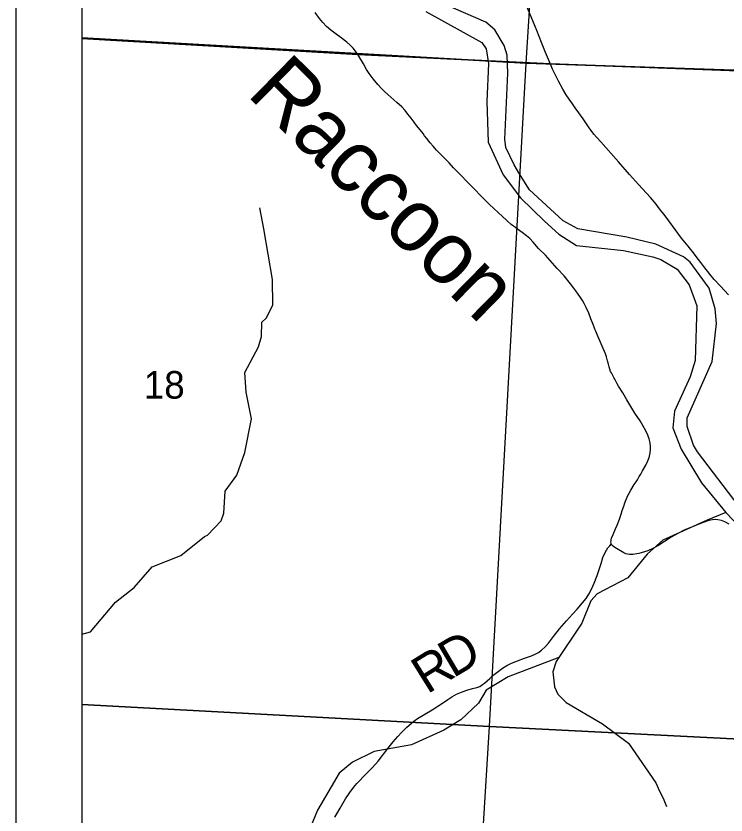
# Model space of a CAD drawing. Extents: x 21.4 to 65.3, y 4 to 26.
# Drawn here: x 23.447 to 24.526, y 19.377 to 20.591 of the extents above; entities that cross this region are included whole.
import ezdxf

# ---------------------------------------------------------------- set-up
doc = ezdxf.new("R2010")
doc.units = 0
for name, color, linetype in [('Default', 7, 'Continuous'), ('GM_X_County_Road', 7, 'Continuous'), ('GM_X_Major_River', 7, 'Continuous'), ('GM_X_Major_River_Text', 7, 'Continuous'), ('GM_X_Minor_River', 7, 'Continuous'), ('GM_X_Section', 7, 'Continuous'), ('GM_X_Section_Text', 7, 'Continuous'), ('GM_X_Township_Road', 7, 'Continuous'), ('GM_X_Township_Road_Text', 7, 'Continuous'), ('SH_Cut_Line', 7, 'Continuous'), ('SH_Data', 7, 'Continuous')]:
    doc.layers.add(name, color=color, linetype=linetype)

msp = doc.modelspace()

# ---------------------------------------------------------------- linework, layer by layer
at = {"layer": 'Default'}
msp.add_lwpolyline([(23.5473, 24.8542), (23.5473, 20.5568), (23.9671, 20.5321), (24.2595, 20.5181), (24.9947, 20.491), (25.2828, 20.4818), (25.7909, 20.4519), (25.8002, 20.4525), (25.809, 20.4526), (25.8187, 20.4522), (25.831, 20.4509), (25.8341, 20.4506), (25.8391, 20.4499), (25.8459, 20.4493), (25.8552, 20.4488), (25.869, 20.4484), (25.878, 20.4484)], dxfattribs=at)
for points in [[(23.5473, 21.5732), (23.5473, 20.5578), (24.2227, 20.5192), (24.2858, 21.5075)], [(23.5473, 20.5578), (23.5473, 19.545), (24.1671, 19.5117), (24.2227, 20.5192)], [(23.5473, 20.5568), (23.5473, 18.0542), (25.1151, 18.0542), (25.1319, 18.358), (25.2037, 19.5236), (25.229, 19.8268), (25.2761, 20.4088), (25.2828, 20.4818), (24.9947, 20.491), (24.2595, 20.5181), (23.9671, 20.5321)], [(23.5473, 19.545), (23.5473, 18.5459), (24.1059, 18.5148), (24.1671, 19.5117)]]:
    msp.add_lwpolyline(points, close=True, dxfattribs=at)
at = {"layer": 'GM_X_County_Road'}
for points in [[(24.2597, 20.5175), (24.252, 20.5351), (24.2459, 20.5506), (24.2423, 20.5598), (24.2389, 20.5686), (24.2363, 20.5747), (24.2227, 20.6076)], [(24.5303, 20.1673), (24.5179, 20.1804), (24.5087, 20.1905), (24.5019, 20.1985), (24.493, 20.2101), (24.4883, 20.2163), (24.4813, 20.2254), (24.477, 20.2311), (24.4687, 20.2412), (24.459, 20.2532), (24.4397, 20.2795), (24.4339, 20.2872), (24.4256, 20.2981), (24.4205, 20.3048), (24.4116, 20.3149), (24.3933, 20.3349), (24.38, 20.35), (24.3632, 20.3693), (24.336, 20.3996), (24.3302, 20.4061), (24.3256, 20.4113), (24.3216, 20.4168), (24.3184, 20.4211), (24.3092, 20.4346), (24.3029, 20.4436), (24.2974, 20.4514), (24.2922, 20.4587), (24.288, 20.4645), (24.2835, 20.4712), (24.2783, 20.4796), (24.2719, 20.4916), (24.2672, 20.501), (24.263, 20.51), (24.2597, 20.5175)]]:
    msp.add_lwpolyline(points, dxfattribs=at)
at = {"layer": 'GM_X_Major_River'}
for points in [[(24.0704, 20.5978), (24.1553, 20.5506), (24.1618, 20.5408), (24.1653, 20.5188), (24.1628, 20.4607), (24.1652, 20.3989), (24.1877, 20.3496), (24.214, 20.3144), (24.2504, 20.2793), (24.2725, 20.2596), (24.299, 20.2423), (24.3707, 20.2345), (24.4154, 20.2248), (24.4275, 20.2211), (24.4522, 20.2064), (24.4704, 20.1825), (24.4823, 20.1507), (24.4795, 20.0676), (24.472, 20.0429), (24.4483, 19.9904), (24.4457, 19.965), (24.4583, 19.9328), (24.4891, 19.8817), (24.5262, 19.8365)], [(24.5463, 19.8457), (24.4833, 19.9287), (24.4772, 19.9389), (24.4673, 19.9674), (24.4672, 19.9803), (24.5052, 20.0662), (24.5119, 20.1239), (24.5099, 20.1459), (24.5008, 20.1773), (24.4719, 20.2171), (24.4616, 20.225), (24.4199, 20.2442), (24.3755, 20.2547), (24.3012, 20.2673), (24.2792, 20.2798), (24.228, 20.3266), (24.2116, 20.3527), (24.2044, 20.3645), (24.1918, 20.391), (24.1902, 20.4035), (24.1949, 20.5037), (24.1937, 20.5314), (24.1895, 20.5458), (24.175, 20.5697), (24.1613, 20.5814), (24.0972, 20.6092)], [(24.5262, 19.8365), (24.5801, 19.7802)]]:
    msp.add_lwpolyline(points, dxfattribs=at)
at = {"layer": 'GM_X_Minor_River'}
for points in [[(23.7632, 19.8356), (23.7654, 19.8691), (23.7828, 19.8931), (23.795, 19.9277), (23.8052, 19.9791), (23.7973, 20.0194), (23.7954, 20.0494), (23.8159, 20.0882), (23.8204, 20.1038), (23.8212, 20.1258), (23.8277, 20.1316), (23.8375, 20.1517), (23.8372, 20.1905), (23.8239, 20.2677), (23.8179, 20.2996)], [(23.5473, 19.6518), (23.5607, 19.6555), (23.5987, 19.7002), (23.627, 19.7228), (23.6544, 19.7542), (23.6977, 19.7715), (23.7337, 19.7999), (23.7383, 19.8021), (23.759, 19.8238), (23.7632, 19.8358)], [(24.5262, 19.8365), (24.4979, 19.825), (24.4302, 19.7946), (24.4064, 19.7732), (24.3774, 19.7374), (24.3657, 19.7313), (24.3305, 19.7132), (24.3211, 19.7022), (24.3072, 19.6687), (24.2685, 19.6104), (24.2633, 19.5944), (24.2657, 19.5716), (24.2711, 19.5607), (24.2837, 19.5478), (24.3389, 19.5154), (24.3782, 19.486), (24.4199, 19.4262), (24.4253, 19.4134), (24.4311, 19.4028), (24.4361, 19.3902)], [(24.2725, 19.6164), (24.1954, 19.5872), (24.1621, 19.5669), (24.1505, 19.5468), (24.1233, 19.5219), (24.0976, 19.5059), (24.0484, 19.4836), (23.9919, 19.4738), (23.9586, 19.4573), (23.9386, 19.4409), (23.9056, 19.3845), (23.8914, 19.3502)]]:
    msp.add_lwpolyline(points, dxfattribs=at)
at = {"layer": 'GM_X_Section'}
for points in [[(25.3384, 21.4821), (25.275, 20.4836), (24.2227, 20.5192), (24.2858, 21.5075), (24.7985, 21.5074)], [(24.2227, 20.5192), (25.275, 20.4836), (25.2871, 20.4832), (25.208, 19.459), (24.1671, 19.5117)], [(24.1671, 19.5117), (25.208, 19.459), (25.1472, 18.4529), (24.1059, 18.5148)]]:
    msp.add_lwpolyline(points, close=True, dxfattribs=at)
at = {"layer": 'GM_X_Township_Road'}
for points in [[(23.9662, 20.5332), (23.9635, 20.5372), (23.9597, 20.542), (23.9554, 20.5464), (23.9503, 20.5508), (23.9415, 20.5576), (23.9395, 20.5591), (23.936, 20.5616), (23.9261, 20.5692), (23.9195, 20.575), (23.9139, 20.5808), (23.9088, 20.5871), (23.9022, 20.5962)], [(24.5312, 19.8188), (24.5246, 19.8222), (24.5195, 19.8242), (24.5141, 19.8256), (24.5099, 19.8261), (24.5057, 19.8257), (24.5004, 19.8245), (24.4916, 19.8213), (24.479, 19.8161), (24.4631, 19.8096), (24.4531, 19.8047), (24.4429, 19.7991), (24.4229, 19.7858), (24.4151, 19.7817), (24.4077, 19.7786), (24.4027, 19.7769), (24.3976, 19.7752), (24.3939, 19.7743), (24.3909, 19.7736), (24.3879, 19.7732), (24.3847, 19.7728), (24.3797, 19.7728), (24.3765, 19.7732), (24.374, 19.7738), (24.3712, 19.7751), (24.3573, 19.7834), (24.3553, 19.785), (24.3536, 19.7863), (24.3527, 19.7874), (24.3521, 19.7886), (24.3517, 19.7901), (24.3516, 19.7919), (24.3517, 19.7939), (24.3519, 19.7956), (24.3526, 19.7976), (24.3548, 19.8031), (24.3558, 19.8057), (24.3584, 19.8116), (24.3611, 19.8176), (24.3644, 19.8267), (24.367, 19.8339), (24.3688, 19.8394), (24.3711, 19.8462), (24.3729, 19.8512), (24.3746, 19.8562), (24.3772, 19.8626), (24.3791, 19.8658), (24.3818, 19.8707), (24.3871, 19.8791), (24.3898, 19.8833), (24.3917, 19.8864), (24.3947, 19.8911), (24.3969, 19.8949), (24.3997, 19.8997), (24.4045, 19.9084), (24.4077, 19.915), (24.4096, 19.9202), (24.4112, 19.9268), (24.4119, 19.9323), (24.4118, 19.9371), (24.4111, 19.9426), (24.4096, 19.9485), (24.4074, 19.9542), (24.4044, 19.9608), (24.3999, 19.9686), (24.3959, 19.9757), (24.388, 19.9876), (24.3756, 20.0078), (24.3695, 20.0186), (24.3633, 20.0287), (24.3608, 20.0323), (24.3576, 20.0389), (24.3567, 20.0405), (24.3556, 20.0426), (24.3533, 20.0469), (24.3522, 20.049), (24.3511, 20.051), (24.35, 20.0545), (24.349, 20.058), (24.348, 20.0617), (24.3464, 20.0671), (24.3447, 20.073), (24.3431, 20.0776), (24.3417, 20.0813), (24.3399, 20.0857), (24.3337, 20.0999), (24.3318, 20.1044), (24.3297, 20.1093), (24.3285, 20.1121), (24.3273, 20.115), (24.3259, 20.1183), (24.3244, 20.1222), (24.3211, 20.131), (24.3181, 20.1395), (24.3141, 20.148), (24.3108, 20.1541), (24.3082, 20.1586), (24.3054, 20.1631), (24.3017, 20.1685), (24.2984, 20.1733), (24.2951, 20.1776), (24.2901, 20.1841), (24.2804, 20.1963), (24.27, 20.2073), (24.2521, 20.2273), (24.2417, 20.2376), (24.2336, 20.2472), (24.2284, 20.2528), (24.2233, 20.2568), (24.2165, 20.2618), (24.213, 20.2645), (24.2096, 20.267), (24.2064, 20.2695), (24.2019, 20.2728), (24.2, 20.2743), (24.1944, 20.2792), (24.193, 20.2805), (24.1866, 20.2863), (24.1668, 20.3043), (24.1594, 20.3118), (24.1387, 20.3331), (24.1181, 20.3545), (24.1124, 20.3603), (24.1056, 20.3675), (24.1004, 20.3728), (24.0939, 20.3795), (24.0866, 20.3871), (24.0812, 20.3929), (24.0769, 20.398), (24.0716, 20.4045), (24.0684, 20.4088), (24.066, 20.4121), (24.0592, 20.4209), (24.0563, 20.4247), (24.0526, 20.4293), (24.0478, 20.4356), (24.0431, 20.4419), (24.0389, 20.4472), (24.0338, 20.4526), (24.0264, 20.4592), (24.017, 20.4673), (24.0123, 20.4714), (24.0074, 20.4761), (24.0022, 20.4814), (23.9973, 20.4868), (23.9903, 20.4952), (23.9841, 20.5034), (23.9802, 20.5095), (23.9753, 20.518), (23.9686, 20.5296), (23.9673, 20.5315), (23.9662, 20.5332)], [(23.9318, 19.3737), (23.9351, 19.3789), (23.9401, 19.3875), (23.9482, 19.4015), (23.9546, 19.4114), (23.9601, 19.4188), (23.9654, 19.4248), (23.9797, 19.4394), (23.9892, 19.4492), (23.9977, 19.4591), (24.0126, 19.4781), (24.0207, 19.4883), (24.0276, 19.4962), (24.0335, 19.5026), (24.0414, 19.5105), (24.0478, 19.5163), (24.0521, 19.5197), (24.0577, 19.5236), (24.0798, 19.5371), (24.0955, 19.5471), (24.1037, 19.5526), (24.1099, 19.5566), (24.1169, 19.5605), (24.1242, 19.5639), (24.1324, 19.5667), (24.1413, 19.5691), (24.148, 19.5708), (24.1521, 19.5725), (24.1563, 19.5752), (24.1593, 19.5774), (24.1635, 19.5809), (24.1674, 19.5844), (24.174, 19.5904), (24.1801, 19.5953), (24.1866, 19.5999), (24.1934, 19.604), (24.2005, 19.6077), (24.2097, 19.6115), (24.2202, 19.6152), (24.2308, 19.6189), (24.2365, 19.6213), (24.2413, 19.6241), (24.2459, 19.6274), (24.2514, 19.6324), (24.2569, 19.6383), (24.2645, 19.6481), (24.2736, 19.6599), (24.2838, 19.6722), (24.293, 19.6823), (24.3002, 19.6899), (24.3085, 19.6992), (24.3139, 19.7061), (24.318, 19.7123), (24.3222, 19.72), (24.3263, 19.7291), (24.3307, 19.7408), (24.3365, 19.7592), (24.3394, 19.768), (24.3429, 19.7759), (24.3448, 19.7796), (24.3469, 19.7831), (24.3497, 19.7862), (24.3521, 19.7886)]]:
    msp.add_lwpolyline(points, dxfattribs=at)
at = {"layer": 'SH_Cut_Line'}
msp.add_lwpolyline([(23.5473, 24.8542), (23.5473, 18.0542), (28.6177, 18.0542)], dxfattribs=at)
at = {"layer": 'SH_Data'}
for p, q in [((23.4473, 24.9542), (23.4473, 17.9542)), ((23.5473, 24.8542), (23.5473, 18.0542))]:
    msp.add_line(p, q, dxfattribs=at)

# ---------------------------------------------------------------- texts
at = {"layer": 'GM_X_Major_River_Text'}
msp.add_text('Raccoon', height=0.0947, rotation=315.5119, dxfattribs=at).set_placement((23.7964, 20.4713))
at = {"layer": 'GM_X_Section_Text'}
msp.add_text('18', height=0.04186, rotation=0, dxfattribs=at).set_placement((23.6415, 20.0096))
at = {"layer": 'GM_X_Township_Road_Text'}
for s, rotation, p in [('D', 30.5858, (24.1114, 19.5843)), ('R', 31.935, (24.0721, 19.5598))]:
    msp.add_text(s, height=0.0568, rotation=rotation, dxfattribs=at).set_placement(p)

doc.saveas('drawing.dxf')
